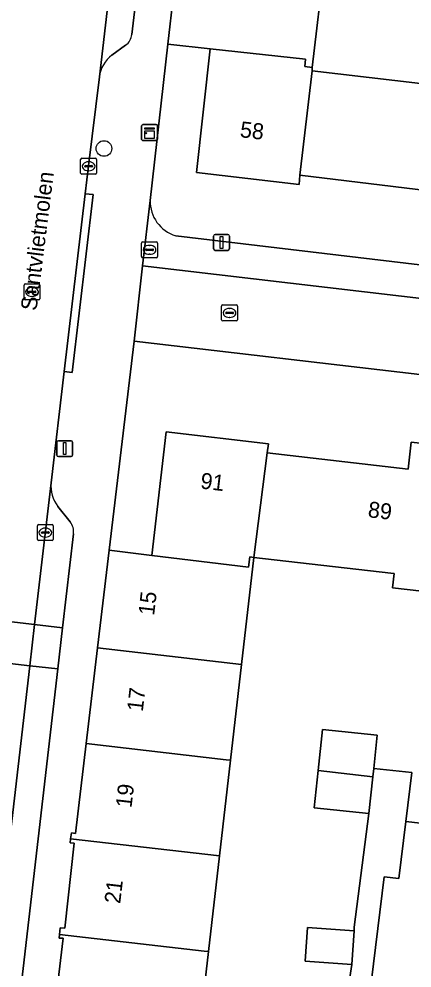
# Model space of a CAD drawing. Extents: x 161241 to 161758, y 384138 to 384885.
# Drawn here: x 161457.1 to 161481.8, y 384527.4 to 384587 of the extents above; entities that cross this region are included whole.
import ezdxf

# ---------------------------------------------------------------- set-up
doc = ezdxf.new("R2010")
doc.units = 0
for name, color, linetype in [('IMGEO_Boom', 7, 'Continuous'), ('IMGEO_Brandkraan', 7, 'Continuous'), ('IMGEO_Erf', 7, 'Continuous'), ('IMGEO_Kast', 7, 'Continuous'), ('IMGEO_Kolk', 7, 'Continuous'), ('IMGEO_Lichtmast', 7, 'Continuous'), ('IMGEO_Openbare_ruimte_label', 7, 'Continuous'), ('IMGEO_Pand', 7, 'Continuous'), ('IMGEO_Pand_nummerreeks', 7, 'Continuous'), ('IMGEO_Parkeervlak_open', 7, 'Continuous'), ('IMGEO_Rijbaan_lokaal_open', 7, 'Continuous'), ('IMGEO_Rioolput', 7, 'Continuous'), ('IMGEO_Voetpad_open', 7, 'Continuous')]:
    doc.layers.add(name, color=color, linetype=linetype)

msp = doc.modelspace()

# ---------------------------------------------------------------- linework, layer by layer
at = {"layer": 'IMGEO_Boom'}
msp.add_circle((161462.46, 384578.862), 0.489, dxfattribs=at)
at = {"layer": 'IMGEO_Brandkraan'}
for p, q in [((161464.815, 384572.077), (161464.815, 384572.929)), ((161464.89, 384573.003), (161465.742, 384573.003)), ((161465.816, 384572.929), (161465.816, 384572.077)), ((161465.074, 384572.497), (161465.074, 384572.509)), ((161465.512, 384572.46), (161465.114, 384572.46)), ((161465.117, 384572.546), (161465.515, 384572.546)), ((161465.303, 384572.783), (161465.328, 384572.783)), ((161465.558, 384572.509), (161465.558, 384572.497)), ((161465.742, 384572.003), (161464.89, 384572.003)), ((161465.326, 384572.223), (161465.301, 384572.223))]:
    msp.add_line(p, q, dxfattribs=at)
for points in [[(161464.815, 384572.077), (161464.815, 384572.929)], [(161464.89, 384573.003), (161465.742, 384573.003)], [(161465.816, 384572.929), (161465.816, 384572.077)], [(161465.742, 384572.003), (161464.89, 384572.003)]]:
    msp.add_lwpolyline(points, dxfattribs=at)
for centre, radius, start, end in [((161464.892, 384572.927), 0.0765, 91.55205, 178.44795), ((161464.892, 384572.927), 0.0765, 91.55205, 178.44795), ((161465.74, 384572.927), 0.0765, 1.55205, 88.44795), ((161465.74, 384572.927), 0.0765, 1.55205, 88.44795), ((161465.114, 384572.506), 0.0403, 85.87752, 175.75265), ((161465.111, 384572.496), 0.0366, 178.93798, 274.71019), ((161465.515, 384572.503), 0.043, 264.86636, 352.45326), ((161465.519, 384572.508), 0.0386, 1.73085, 96.63898), ((161464.892, 384572.079), 0.0765, 181.55205, 268.44795), ((161464.892, 384572.079), 0.0765, 181.55205, 268.44795), ((161465.74, 384572.079), 0.0765, 271.55205, 358.44795), ((161465.74, 384572.079), 0.0765, 271.55205, 358.44795)]:
    msp.add_arc(centre, radius, start, end, dxfattribs=at)
for centre, major_axis, ratio, start_param, end_param in [((161465.302, 384572.503), (-0.387, 0.002), 0.722429, 4.712389, 7.853982), ((161465.327, 384572.503), (-0.39, 0.002), 0.717154, 1.570796, 4.712389)]:
    msp.add_ellipse(centre, major_axis=major_axis, ratio=ratio, start_param=start_param, end_param=end_param, dxfattribs=at)
at = {"layer": 'IMGEO_Erf'}
for points in [[(161476.271, 384590.5), (161475.503, 384583.942), (161475.502, 384583.743), (161484.26, 384582.718)], [(161483.517, 384576.132), (161474.735, 384577.196), (161474.694, 384576.61), (161468.258, 384577.355), (161469.124, 384585.125), (161466.461, 384585.408), (161465.355, 384575.608)], [(161466.953, 384573.387), (161500, 384569.458), (161516.744, 384567.467)], [(161482.25, 384564.675), (161464.362, 384566.766), (161462.781, 384553.656), (161465.466, 384553.329), (161466.359, 384561.082), (161472.764, 384560.327), (161472.692, 384559.759), (161481.523, 384558.733), (161481.721, 384560.427), (161487.838, 384559.733)], [(161486.778, 384550.579), (161480.542, 384551.296), (161480.645, 384552.191), (161480.438, 384552.215), (161471.853, 384553.203), (161471.079, 384546.471), (161470.388, 384540.466), (161469.698, 384534.463), (161469.007, 384528.458), (161468.317, 384522.455)], [(161477.504, 384524.509), (161477.986, 384527.66), (161475.067, 384527.863), (161475.213, 384529.966), (161478.133, 384529.762), (161478.149, 384529.998), (161479.067, 384537.13), (161475.629, 384537.492), (161475.875, 384539.831), (161476.145, 384542.396), (161479.584, 384542.034), (161479.365, 384539.957), (161481.755, 384539.706), (161481.372, 384536.621), (161488.548, 384535.801)]]:
    msp.add_lwpolyline(points, dxfattribs=at)
msp.add_arc((161467.617, 384575.55), 2.263, 178.53531, 252.9344, dxfattribs=at)
at = {"layer": 'IMGEO_Kast'}
for p, q in [((161464.82, 384579.437), (161464.82, 384580.278)), ((161464.82, 384580.278), (161464.82, 384579.437)), ((161464.895, 384580.362), (161465.736, 384580.362)), ((161465.736, 384580.362), (161464.895, 384580.362)), ((161465.82, 384580.287), (161465.82, 384579.446)), ((161465.82, 384579.446), (161465.82, 384580.287)), ((161465.745, 384579.362), (161464.904, 384579.362)), ((161464.904, 384579.362), (161465.745, 384579.362))]:
    msp.add_line(p, q, dxfattribs=at)
for points in [[(161465.015, 384580.152), (161465.615, 384580.152), (161465.615, 384580.067), (161465.015, 384580.067), (161465.015, 384580.152)], [(161465.015, 384579.977), (161465.615, 384579.977), (161465.615, 384579.488), (161465.015, 384579.488), (161465.015, 384579.977)]]:
    msp.add_lwpolyline(points, dxfattribs=at)
msp.add_circle((161465.099, 384579.826), 0.0377, dxfattribs=at)
for centre, start, end in [((161464.898, 384580.284), 92.4484, 184.28452), ((161464.898, 384580.284), 92.4484, 184.28452), ((161465.742, 384580.284), 2.4484, 94.28452), ((161465.742, 384580.284), 2.4484, 94.28452), ((161464.898, 384579.44), 182.4484, 274.28452), ((161464.898, 384579.44), 182.4484, 274.28452), ((161465.742, 384579.44), 272.4484, 4.28452), ((161465.742, 384579.44), 272.4484, 4.28452)]:
    msp.add_arc(centre, 0.0779, start, end, dxfattribs=at)
at = {"layer": 'IMGEO_Kolk'}
for p, q in [((161460.998, 384577.322), (161460.998, 384578.174)), ((161461.073, 384578.248), (161461.925, 384578.248)), ((161461.257, 384577.742), (161461.257, 384577.754)), ((161461.695, 384577.705), (161461.297, 384577.705)), ((161461.3, 384577.791), (161461.698, 384577.791)), ((161461.486, 384578.028), (161461.511, 384578.028)), ((161461.741, 384577.754), (161461.741, 384577.742)), ((161461.999, 384578.174), (161461.999, 384577.322)), ((161461.925, 384577.248), (161461.073, 384577.248)), ((161461.509, 384577.468), (161461.484, 384577.468)), ((161469.828, 384568.117), (161469.828, 384568.969)), ((161469.903, 384569.043), (161470.755, 384569.043)), ((161470.316, 384568.823), (161470.341, 384568.823)), ((161470.829, 384568.969), (161470.829, 384568.117)), ((161470.087, 384568.537), (161470.087, 384568.549)), ((161470.525, 384568.5), (161470.127, 384568.5)), ((161470.13, 384568.586), (161470.528, 384568.586)), ((161470.339, 384568.263), (161470.314, 384568.263)), ((161470.571, 384568.549), (161470.571, 384568.537)), ((161470.755, 384568.043), (161469.903, 384568.043)), ((161458.285, 384554.33), (161458.285, 384555.182)), ((161458.36, 384555.256), (161459.212, 384555.256)), ((161458.773, 384555.036), (161458.798, 384555.036)), ((161459.286, 384555.182), (161459.286, 384554.33)), ((161458.544, 384554.75), (161458.544, 384554.762)), ((161458.982, 384554.713), (161458.584, 384554.713)), ((161458.587, 384554.799), (161458.985, 384554.799)), ((161458.796, 384554.476), (161458.771, 384554.476)), ((161459.028, 384554.762), (161459.028, 384554.75)), ((161459.212, 384554.256), (161458.36, 384554.256))]:
    msp.add_line(p, q, dxfattribs=at)
for points in [[(161460.998, 384577.322), (161460.998, 384578.174)], [(161461.073, 384578.248), (161461.925, 384578.248)], [(161461.999, 384578.174), (161461.999, 384577.322)], [(161461.925, 384577.248), (161461.073, 384577.248)], [(161469.828, 384568.117), (161469.828, 384568.969)], [(161469.903, 384569.043), (161470.755, 384569.043)], [(161470.829, 384568.969), (161470.829, 384568.117)], [(161470.755, 384568.043), (161469.903, 384568.043)], [(161458.285, 384554.33), (161458.285, 384555.182)], [(161458.36, 384555.256), (161459.212, 384555.256)], [(161459.286, 384555.182), (161459.286, 384554.33)], [(161459.212, 384554.256), (161458.36, 384554.256)]]:
    msp.add_lwpolyline(points, dxfattribs=at)
for centre, radius, start, end in [((161461.075, 384578.172), 0.0765, 91.55205, 178.44795), ((161461.075, 384578.172), 0.0765, 91.55205, 178.44795), ((161461.297, 384577.751), 0.0403, 85.87752, 175.75265), ((161461.294, 384577.741), 0.0366, 178.93798, 274.71019), ((161461.698, 384577.748), 0.043, 264.86636, 352.45326), ((161461.702, 384577.753), 0.0386, 1.73085, 96.63898), ((161461.923, 384578.172), 0.0765, 1.55205, 88.44795), ((161461.923, 384578.172), 0.0765, 1.55205, 88.44795), ((161461.075, 384577.324), 0.0765, 181.55205, 268.44795), ((161461.075, 384577.324), 0.0765, 181.55205, 268.44795), ((161461.923, 384577.324), 0.0765, 271.55205, 358.44795), ((161461.923, 384577.324), 0.0765, 271.55205, 358.44795), ((161469.905, 384568.967), 0.0765, 91.55205, 178.44795), ((161469.905, 384568.967), 0.0765, 91.55205, 178.44795), ((161470.753, 384568.967), 0.0765, 1.55205, 88.44795), ((161470.753, 384568.967), 0.0765, 1.55205, 88.44795), ((161470.127, 384568.546), 0.0403, 85.87752, 175.75265), ((161470.124, 384568.536), 0.0366, 178.93798, 274.71019), ((161470.528, 384568.543), 0.043, 264.86636, 352.45326), ((161470.532, 384568.548), 0.0386, 1.73085, 96.63898), ((161469.905, 384568.119), 0.0765, 181.55205, 268.44795), ((161469.905, 384568.119), 0.0765, 181.55205, 268.44795), ((161470.753, 384568.119), 0.0765, 271.55205, 358.44795), ((161470.753, 384568.119), 0.0765, 271.55205, 358.44795), ((161458.362, 384555.18), 0.0765, 91.55205, 178.44795), ((161458.362, 384555.18), 0.0765, 91.55205, 178.44795), ((161459.21, 384555.18), 0.0765, 1.55205, 88.44795), ((161459.21, 384555.18), 0.0765, 1.55205, 88.44795), ((161458.584, 384554.759), 0.0403, 85.87752, 175.75265), ((161458.581, 384554.749), 0.0366, 178.93798, 274.71019), ((161458.985, 384554.756), 0.043, 264.86636, 352.45326), ((161458.989, 384554.761), 0.0386, 1.73085, 96.63898), ((161458.362, 384554.332), 0.0765, 181.55205, 268.44795), ((161458.362, 384554.332), 0.0765, 181.55205, 268.44795), ((161459.21, 384554.332), 0.0765, 271.55205, 358.44795), ((161459.21, 384554.332), 0.0765, 271.55205, 358.44795)]:
    msp.add_arc(centre, radius, start, end, dxfattribs=at)
for centre, major_axis, ratio, start_param, end_param in [((161461.485, 384577.748), (-0.387, 0.002), 0.722429, 4.712389, 7.853982), ((161461.51, 384577.748), (-0.39, 0.002), 0.717154, 1.570796, 4.712389), ((161470.315, 384568.543), (-0.387, 0.002), 0.722429, 4.712389, 7.853982), ((161470.34, 384568.543), (-0.39, 0.002), 0.717154, 1.570796, 4.712389), ((161458.772, 384554.756), (-0.387, 0.002), 0.722429, 4.712389, 7.853982), ((161458.797, 384554.756), (-0.39, 0.002), 0.717154, 1.570796, 4.712389)]:
    msp.add_ellipse(centre, major_axis=major_axis, ratio=ratio, start_param=start_param, end_param=end_param, dxfattribs=at)
at = {"layer": 'IMGEO_Lichtmast'}
for p, q in [((161469.331, 384572.566), (161469.331, 384573.366)), ((161469.331, 384573.366), (161469.331, 384572.566)), ((161469.431, 384573.466), (161470.221, 384573.466)), ((161470.221, 384573.466), (161469.431, 384573.466)), ((161470.321, 384573.366), (161470.321, 384572.566)), ((161470.321, 384572.566), (161470.321, 384573.366)), ((161470.221, 384572.466), (161469.431, 384572.466)), ((161469.431, 384572.466), (161470.221, 384572.466)), ((161459.507, 384559.626), (161459.507, 384560.426)), ((161459.507, 384560.426), (161459.507, 384559.626)), ((161459.607, 384560.526), (161460.397, 384560.526)), ((161460.397, 384560.526), (161459.607, 384560.526)), ((161460.497, 384560.426), (161460.497, 384559.626)), ((161460.497, 384559.626), (161460.497, 384560.426)), ((161460.397, 384559.526), (161459.607, 384559.526)), ((161459.607, 384559.526), (161460.397, 384559.526))]:
    msp.add_line(p, q, dxfattribs=at)
for points in [[(161469.751, 384573.341), (161469.901, 384573.341), (161469.901, 384572.591), (161469.751, 384572.591), (161469.751, 384573.341)], [(161459.927, 384560.401), (161460.077, 384560.401), (161460.077, 384559.651), (161459.927, 384559.651), (161459.927, 384560.401)]]:
    msp.add_lwpolyline(points, dxfattribs=at)
for centre, start, end in [((161469.431, 384573.366), 90, 180), ((161469.431, 384573.366), 90, 180), ((161470.221, 384573.366), 0, 90), ((161470.221, 384573.366), 360, 90), ((161469.431, 384572.566), 180, 270), ((161469.431, 384572.566), 180, 270), ((161470.221, 384572.566), 270, 0), ((161470.221, 384572.566), 270, 0), ((161459.607, 384560.426), 90, 180), ((161459.607, 384560.426), 90, 180), ((161460.397, 384560.426), 0, 90), ((161460.397, 384560.426), 360, 90), ((161459.607, 384559.626), 180, 270), ((161459.607, 384559.626), 180, 270), ((161460.397, 384559.626), 270, 0), ((161460.397, 384559.626), 270, 0)]:
    msp.add_arc(centre, 0.1, start, end, dxfattribs=at)
at = {"layer": 'IMGEO_Pand'}
for points in [[(161466.461, 384585.408), (161469.124, 384585.125), (161475.091, 384584.461), (161475.04, 384584), (161475.503, 384583.942), (161476.271, 384590.5), (161475.852, 384590.552), (161467.179, 384591.626)], [(161469.124, 384585.125), (161468.258, 384577.355), (161474.694, 384576.61), (161474.735, 384577.196), (161475.502, 384583.743), (161475.503, 384583.942), (161475.04, 384584), (161475.091, 384584.461)], [(161490.562, 384582.885), (161484.364, 384583.611), (161484.26, 384582.718), (161475.502, 384583.743), (161474.735, 384577.196), (161483.517, 384576.132), (161483.32, 384574.444), (161489.48, 384573.718)], [(161471.853, 384553.203), (161472.692, 384559.759), (161472.764, 384560.327), (161466.359, 384561.082), (161465.466, 384553.329), (161471.52, 384552.597), (161471.597, 384553.232)], [(161471.853, 384553.203), (161480.438, 384552.215), (161480.645, 384552.191), (161480.542, 384551.296), (161486.778, 384550.579), (161487.838, 384559.733), (161481.721, 384560.427), (161481.523, 384558.733), (161472.692, 384559.759)], [(161462.056, 384547.515), (161471.079, 384546.471), (161471.853, 384553.203), (161471.597, 384553.232), (161471.52, 384552.597), (161465.466, 384553.329), (161462.781, 384553.656)], [(161461.348, 384541.513), (161470.123, 384540.497), (161470.388, 384540.466), (161471.079, 384546.471), (161462.056, 384547.515)], [(161479.584, 384542.034), (161476.145, 384542.396), (161475.875, 384539.831), (161479.31, 384539.433), (161479.365, 384539.957)], [(161460.683, 384535.879), (161460.415, 384535.921), (161460.369, 384535.543), (161469.698, 384534.463), (161470.388, 384540.466), (161470.123, 384540.497), (161461.348, 384541.513)], [(161479.31, 384539.433), (161475.875, 384539.831), (161475.629, 384537.492), (161479.067, 384537.13)], [(161460.337, 384535.278), (161460.601, 384535.258), (161460.008, 384529.927), (161459.712, 384529.959), (161459.667, 384529.54), (161468.733, 384528.49), (161469.007, 384528.458), (161469.698, 384534.463), (161460.369, 384535.543)], [(161459.642, 384529.306), (161459.894, 384529.296), (161459.223, 384523.508), (161468.317, 384522.455), (161469.007, 384528.458), (161468.733, 384528.49), (161459.667, 384529.54)], [(161478.133, 384529.762), (161475.213, 384529.966), (161475.067, 384527.863), (161477.986, 384527.66)]]:
    msp.add_lwpolyline(points, close=True, dxfattribs=at)
at = {"layer": 'IMGEO_Parkeervlak_open'}
for points in [[(161467.711, 384630.934), (161465.22, 384609.545), (161464.9, 384606.794), (161462.171, 384583.365)], [(161464.207, 384586.016), (161469.135, 384627.927)], [(161462.961, 384584.717), (161463.819, 384585.349)], [(161459.149, 384557.883), (161458.115, 384548.986), (161459.867, 384548.782), (161460.551, 384554.685)], [(161460.343, 384555.425), (161459.571, 384556.403)], [(161455.567, 384511.666), (161459.568, 384546.2), (161457.814, 384546.404), (161453.447, 384508.842)]]:
    msp.add_lwpolyline(points, dxfattribs=at)
msp.add_lwpolyline([(161457.814, 384546.404), (161459.568, 384546.2), (161459.867, 384548.782), (161458.115, 384548.986)], close=True, dxfattribs=at)
for centre, radius, start, end in [((161463.252, 384586.125), 0.961, 306.13642, 353.48967), ((161464.127, 384583.129), 1.97, 126.28644, 173.11641), ((161461.161, 384557.657), 2.025, 173.57824, 218.25119), ((161459.56, 384554.806), 0.999, 353.06428, 38.33505)]:
    msp.add_arc(centre, radius, start, end, dxfattribs=at)
at = {"layer": 'IMGEO_Rijbaan_lokaal_open'}
for points in [[(161458.88, 384607.496), (161456.155, 384584.108), (161455.501, 384578.293), (161455.326, 384576.798), (161454.02, 384565.608), (161453.187, 384558.455), (161452.178, 384549.677), (161458.115, 384548.986), (161459.149, 384557.883), (161459.972, 384564.87), (161461.287, 384576.027), (161461.494, 384577.785), (161462.171, 384583.365), (161464.9, 384606.794)], [(161549.997, 384563.724), (161552.363, 384584.51), (161546.893, 384585.147), (161545.138, 384570.12), (161544.805, 384567.256), (161544.482, 384564.358), (161544.235, 384562.197), (161526.561, 384564.282), (161512.889, 384565.866), (161500, 384567.378), (161464.869, 384571.501), (161464.362, 384566.766), (161482.25, 384564.675), (161500, 384562.593), (161511.694, 384561.211), (161511.799, 384561.199), (161533.354, 384558.711), (161529.608, 384527.209), (161529.045, 384522.471), (161532.06, 384522.097), (161534.304, 384521.808), (161539.084, 384521.135), (161547.01, 384536.791)], [(161452.178, 384549.677), (161451.881, 384547.095), (161457.814, 384546.404), (161458.115, 384548.986)]]:
    msp.add_lwpolyline(points, close=True, dxfattribs=at)
for points in [[(161452.684, 384502.539), (161453.058, 384505.828), (161453.447, 384508.842), (161457.814, 384546.404), (161451.881, 384547.095), (161451.359, 384542.556), (161447.539, 384509.648), (161446.771, 384503.468)], [(161529.608, 384527.209), (161526.614, 384527.621), (161521.648, 384528.2), (161517.508, 384528.682), (161507.384, 384530.01), (161507.345, 384529.633), (161505.157, 384529.86), (161505.196, 384530.237), (161498.788, 384530.902), (161498.703, 384530.087), (161496.367, 384530.328), (161496.373, 384530.385), (161492.831, 384530.751), (161490.585, 384530.988), (161488.057, 384531.255), (161488.143, 384532.076), (161488.389, 384534.407), (161488.548, 384535.801), (161481.372, 384536.621), (161480.929, 384533.054), (161480.018, 384533.151), (161478.689, 384522.238)]]:
    msp.add_lwpolyline(points, dxfattribs=at)
at = {"layer": 'IMGEO_Rioolput'}
for p, q in [((161457.449, 384569.435), (161457.449, 384570.287)), ((161457.524, 384570.361), (161458.376, 384570.361)), ((161457.937, 384570.141), (161457.962, 384570.141)), ((161458.45, 384570.287), (161458.45, 384569.435)), ((161458.376, 384569.361), (161457.524, 384569.361)), ((161457.708, 384569.855), (161457.708, 384569.867)), ((161458.146, 384569.818), (161457.748, 384569.818)), ((161457.751, 384569.904), (161458.149, 384569.904)), ((161457.96, 384569.581), (161457.935, 384569.581)), ((161458.192, 384569.867), (161458.192, 384569.855))]:
    msp.add_line(p, q, dxfattribs=at)
for points in [[(161457.449, 384569.435), (161457.449, 384570.287)], [(161457.524, 384570.361), (161458.376, 384570.361)], [(161458.45, 384570.287), (161458.45, 384569.435)], [(161458.376, 384569.361), (161457.524, 384569.361)]]:
    msp.add_lwpolyline(points, dxfattribs=at)
for centre, radius, start, end in [((161457.526, 384570.285), 0.0765, 91.55205, 178.44795), ((161457.526, 384570.285), 0.0765, 91.55205, 178.44795), ((161458.374, 384570.285), 0.0765, 1.55205, 88.44795), ((161458.374, 384570.285), 0.0765, 1.55205, 88.44795), ((161457.526, 384569.437), 0.0765, 181.55205, 268.44795), ((161457.526, 384569.437), 0.0765, 181.55205, 268.44795), ((161457.748, 384569.864), 0.0403, 85.87752, 175.75265), ((161457.745, 384569.854), 0.0366, 178.93798, 274.71019), ((161458.149, 384569.861), 0.043, 264.86636, 352.45326), ((161458.153, 384569.866), 0.0386, 1.73085, 96.63898), ((161458.374, 384569.437), 0.0765, 271.55205, 358.44795), ((161458.374, 384569.437), 0.0765, 271.55205, 358.44795)]:
    msp.add_arc(centre, radius, start, end, dxfattribs=at)
for centre, major_axis, ratio, start_param, end_param in [((161457.936, 384569.861), (-0.387, 0.002), 0.722429, 4.712389, 7.853982), ((161457.961, 384569.861), (-0.39, 0.002), 0.717154, 1.570796, 4.712389)]:
    msp.add_ellipse(centre, major_axis=major_axis, ratio=ratio, start_param=start_param, end_param=end_param, dxfattribs=at)
at = {"layer": 'IMGEO_Voetpad_open'}
for points in [[(161469.135, 384627.927), (161464.207, 384586.016)], [(161461.348, 384541.513), (161462.056, 384547.515), (161462.781, 384553.656), (161464.362, 384566.766), (161464.869, 384571.501), (161465.355, 384575.608), (161466.461, 384585.408), (161467.179, 384591.626)], [(161463.819, 384585.349), (161462.961, 384584.717)], [(161462.171, 384583.365), (161461.494, 384577.785), (161461.287, 384576.027), (161461.783, 384575.969), (161460.468, 384564.812), (161459.972, 384564.87), (161459.149, 384557.883)], [(161465.355, 384575.608), (161464.869, 384571.501), (161500, 384567.378), (161512.889, 384565.866)], [(161516.744, 384567.467), (161500, 384569.458), (161466.953, 384573.387)], [(161459.571, 384556.403), (161460.343, 384555.425)], [(161460.551, 384554.685), (161459.867, 384548.782), (161459.568, 384546.2), (161455.567, 384511.666)], [(161456.261, 384497.821), (161456.511, 384500), (161457.818, 384511.391), (161458.527, 384517.504), (161459.223, 384523.508), (161459.894, 384529.296), (161459.642, 384529.306), (161459.667, 384529.54), (161459.712, 384529.959), (161460.008, 384529.927), (161460.601, 384535.258), (161460.337, 384535.278), (161460.369, 384535.543), (161460.415, 384535.921), (161460.683, 384535.879), (161461.348, 384541.513)]]:
    msp.add_lwpolyline(points, dxfattribs=at)
for points in [[(161461.287, 384576.027), (161459.972, 384564.87), (161460.468, 384564.812), (161461.783, 384575.969)], [(161480.018, 384533.151), (161480.929, 384533.054), (161481.372, 384536.621), (161481.755, 384539.706), (161479.365, 384539.957), (161479.31, 384539.433), (161479.067, 384537.13), (161478.149, 384529.998), (161478.133, 384529.762), (161477.986, 384527.66), (161477.504, 384524.509), (161477.437, 384523.786), (161477.219, 384521.424), (161477.002, 384519.077), (161476.699, 384515.881), (161477.99, 384515.77), (161478.689, 384522.238)]]:
    msp.add_lwpolyline(points, close=True, dxfattribs=at)
for centre, radius, start, end in [((161463.252, 384586.125), 0.961, 306.13642, 353.48967), ((161464.127, 384583.129), 1.97, 126.28644, 173.11641), ((161467.617, 384575.55), 2.263, 178.53531, 252.9344), ((161461.161, 384557.657), 2.025, 173.57824, 218.25119), ((161459.56, 384554.806), 0.999, 353.06428, 38.33505)]:
    msp.add_arc(centre, radius, start, end, dxfattribs=at)

# ---------------------------------------------------------------- texts
at = {"layer": 'IMGEO_Openbare_ruimte_label'}
msp.add_text('Santvlietmolen', height=1, rotation=82.81812, dxfattribs=at).set_placement((161458.228, 384568.646))
at = {"layer": 'IMGEO_Pand_nummerreeks'}
for s, rotation, p in [('58', 353.39711, (161470.947, 384579.58)), ('91', 353.27719, (161468.469, 384557.531)), ('89', 353.37299, (161478.966, 384555.728)), ('15', 83.30267, (161465.599, 384549.524)), ('17', 83.30267, (161464.89, 384543.486)), ('19', 83.30267, (161464.181, 384537.448)), ('21', 83.30267, (161463.475, 384531.432))]:
    msp.add_text(s, height=1, rotation=rotation, dxfattribs=at).set_placement(p)

doc.saveas('drawing.dxf')
